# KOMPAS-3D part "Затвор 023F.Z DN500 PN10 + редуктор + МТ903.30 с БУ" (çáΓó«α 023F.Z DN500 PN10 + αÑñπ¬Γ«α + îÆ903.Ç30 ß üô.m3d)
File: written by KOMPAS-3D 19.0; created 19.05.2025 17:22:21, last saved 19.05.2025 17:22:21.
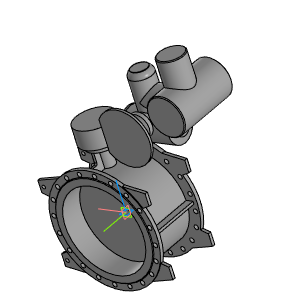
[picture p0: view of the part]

Document properties: Полное имя файла: Затвор 023F.Z DN500 PN10 + редуктор + МТ903.30 с БУ.a3d

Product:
- Part/product: Затвор 023F.Z DN500 PN10 + редуктор + МТ903.30 с БУ
    Масса: 553.483

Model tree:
1. Операция без истории:1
